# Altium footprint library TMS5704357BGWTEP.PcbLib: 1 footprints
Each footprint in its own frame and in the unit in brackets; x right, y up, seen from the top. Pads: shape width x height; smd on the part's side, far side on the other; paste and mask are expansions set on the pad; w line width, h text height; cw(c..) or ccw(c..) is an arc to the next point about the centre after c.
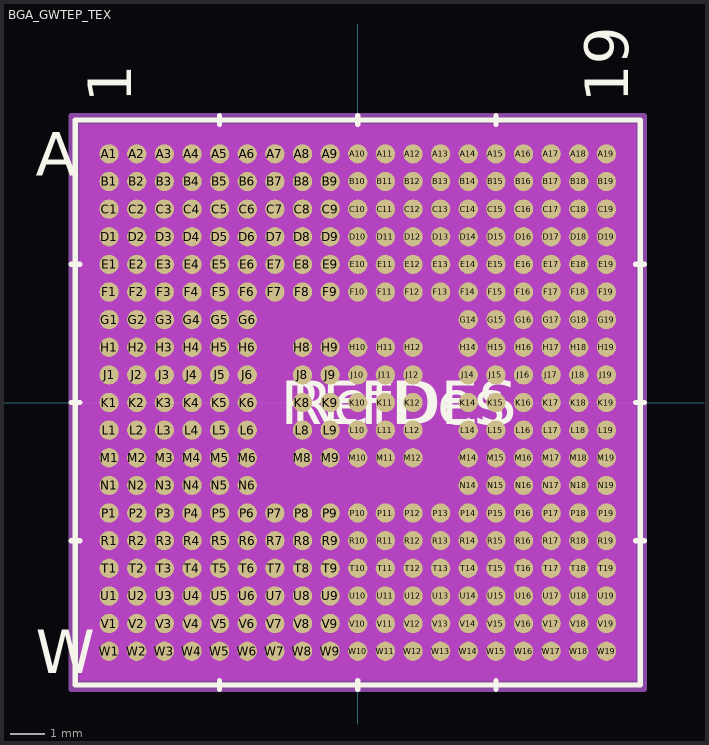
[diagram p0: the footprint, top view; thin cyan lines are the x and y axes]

## BGA_GWTEP_TEX [mil]
pads (337):
  round 22 smd paste+0 mask+0: A1(-283.46,283.5) A2(-251.97,283.5) A3(-220.47,283.5) A4(-188.98,283.5) A5(-157.48,283.5) A6(-125.98,283.5) A7(-94.49,283.5) A8(-62.99,283.5) A9(-31.5,283.5) A10(0,283.5) A11(31.5,283.5) A12(62.99,283.5) A13(94.49,283.5) A14(125.98,283.5) A15(157.48,283.5) A16(188.98,283.5) A17(220.47,283.5) A18(251.97,283.5) A19(283.46,283.5) B1(-283.46,252) B2(-251.97,252) B3(-220.47,252) B4(-188.98,252) B5(-157.48,252) B6(-125.98,252) B7(-94.49,252) B8(-62.99,252) B9(-31.5,252) B10(0,252) B11(31.5,252) B12(62.99,252) B13(94.49,252) B14(125.98,252) B15(157.48,252) B16(188.98,252) B17(220.47,252) B18(251.97,252) B19(283.46,252) C1(-283.46,220.5) C2(-251.97,220.5) C3(-220.47,220.5) C4(-188.98,220.5) C5(-157.48,220.5) C6(-125.98,220.5) C7(-94.49,220.5) C8(-62.99,220.5) C9(-31.5,220.5) C10(0,220.5) C11(31.5,220.5) C12(62.99,220.5) C13(94.49,220.5) C14(125.98,220.5) C15(157.48,220.5) C16(188.98,220.5) C17(220.47,220.5) C18(251.97,220.5) C19(283.46,220.5) D1(-283.46,189) D2(-251.97,189) D3(-220.47,189) D4(-188.98,189) D5(-157.48,189) D6(-125.98,189) D7(-94.49,189) D8(-62.99,189) D9(-31.5,189) D10(0,189) D11(31.5,189) D12(62.99,189) D13(94.49,189) D14(125.98,189) D15(157.48,189) D16(188.98,189) D17(220.47,189) D18(251.97,189) D19(283.46,189) E1(-283.46,157.5) E2(-251.97,157.5) E3(-220.47,157.5) E4(-188.98,157.5) E5(-157.48,157.5) E6(-125.98,157.5) E7(-94.49,157.5) E8(-62.99,157.5) E9(-31.5,157.5) E10(0,157.5) E11(31.5,157.5) E12(62.99,157.5) E13(94.49,157.5) E14(125.98,157.5) E15(157.48,157.5) E16(188.98,157.5) E17(220.47,157.5) E18(251.97,157.5) E19(283.46,157.5) F1(-283.46,126) F2(-251.97,126) F3(-220.47,126) F4(-188.98,126) F5(-157.48,126) F6(-125.98,126) F7(-94.49,126) F8(-62.99,126) F9(-31.5,126) F10(0,126) F11(31.5,126) F12(62.99,126) F13(94.49,126) F14(125.98,126) F15(157.48,126) F16(188.98,126) F17(220.47,126) F18(251.97,126) F19(283.46,126) G1(-283.46,94.5) G2(-251.97,94.5) G3(-220.47,94.5) G4(-188.98,94.5) G5(-157.48,94.5) G6(-125.98,94.5) G14(125.98,94.5) G15(157.48,94.5) G16(188.98,94.5) G17(220.47,94.5) G18(251.97,94.5) G19(283.46,94.5) H1(-283.46,63) H2(-251.97,63) H3(-220.47,63) H4(-188.98,63) H5(-157.48,63) H6(-125.98,63) H8(-62.99,63) H9(-31.5,63) H10(0,63) H11(31.5,63) H12(62.99,63) H14(125.98,63) H15(157.48,63) H16(188.98,63) H17(220.47,63) H18(251.97,63) H19(283.46,63) J1(-283.46,31.5) J2(-251.97,31.5) J3(-220.47,31.5) J4(-188.98,31.5) J5(-157.48,31.5) J6(-125.98,31.5) J8(-62.99,31.5) J9(-31.5,31.5) J10(0,31.5) J11(31.5,31.5) J12(62.99,31.5) J14(125.98,31.5) J15(157.48,31.5) J16(188.98,31.5) J17(220.47,31.5) J18(251.97,31.5) J19(283.46,31.5) K1(-283.46,0) K2(-251.97,0) K3(-220.47,0) K4(-188.98,0) K5(-157.48,0) K6(-125.98,0) K8(-62.99,0) K9(-31.5,0) K10(0,0) K11(31.5,0) K12(62.99,0) K14(125.98,0) K15(157.48,0) K16(188.98,0) K17(220.47,0) K18(251.97,0) K19(283.46,0) L1(-283.46,-31.5) L2(-251.97,-31.5) L3(-220.47,-31.5) L4(-188.98,-31.5) L5(-157.48,-31.5) L6(-125.98,-31.5) L8(-62.99,-31.5) L9(-31.5,-31.5) L10(0,-31.5) L11(31.5,-31.5) L12(62.99,-31.5) L14(125.98,-31.5) L15(157.48,-31.5) L16(188.98,-31.5) L17(220.47,-31.5) L18(251.97,-31.5) L19(283.46,-31.5) M1(-283.46,-63) M2(-251.97,-63) M3(-220.47,-63) M4(-188.98,-63) M5(-157.48,-63) M6(-125.98,-63) M8(-62.99,-63) M9(-31.5,-63) M10(0,-63) M11(31.5,-63) M12(62.99,-63) M14(125.98,-63) M15(157.48,-63) M16(188.98,-63) M17(220.47,-63) M18(251.97,-63) M19(283.46,-63) N1(-283.46,-94.5) N2(-251.97,-94.5) N3(-220.47,-94.5) N4(-188.98,-94.5) N5(-157.48,-94.5) N6(-125.98,-94.5) N14(125.98,-94.5) N15(157.48,-94.5) N16(188.98,-94.5) N17(220.47,-94.5) N18(251.97,-94.5) N19(283.46,-94.5) P1(-283.46,-126) P2(-251.97,-126) P3(-220.47,-126) P4(-188.98,-126) P5(-157.48,-126) P6(-125.98,-126) P7(-94.49,-126) P8(-62.99,-126) P9(-31.5,-126) P10(0,-126) P11(31.5,-126) P12(62.99,-126) P13(94.49,-126) P14(125.98,-126) P15(157.48,-126) P16(188.98,-126) P17(220.47,-126) P18(251.97,-126) P19(283.46,-126) R1(-283.46,-157.5) R2(-251.97,-157.5) R3(-220.47,-157.5) R4(-188.98,-157.5) R5(-157.48,-157.5) R6(-125.98,-157.5) R7(-94.49,-157.5) R8(-62.99,-157.5) R9(-31.5,-157.5) R10(0,-157.5) R11(31.5,-157.5) R12(62.99,-157.5) R13(94.49,-157.5) R14(125.98,-157.5) R15(157.48,-157.5) R16(188.98,-157.5) R17(220.47,-157.5) R18(251.97,-157.5) R19(283.46,-157.5) T1(-283.46,-189) T2(-251.97,-189) T3(-220.47,-189) T4(-188.98,-189) T5(-157.48,-189) T6(-125.98,-189) T7(-94.49,-189) T8(-62.99,-189) T9(-31.5,-189) T10(0,-189) T11(31.5,-189) T12(62.99,-189) T13(94.49,-189) T14(125.98,-189) T15(157.48,-189) T16(188.98,-189) T17(220.47,-189) T18(251.97,-189) T19(283.46,-189) U1(-283.46,-220.5) U2(-251.97,-220.5) U3(-220.47,-220.5) U4(-188.98,-220.5) U5(-157.48,-220.5) U6(-125.98,-220.5) U7(-94.49,-220.5) U8(-62.99,-220.5) U9(-31.5,-220.5) U10(0,-220.5) U11(31.5,-220.5) U12(62.99,-220.5) U13(94.49,-220.5) U14(125.98,-220.5) U15(157.48,-220.5) U16(188.98,-220.5) U17(220.47,-220.5) U18(251.97,-220.5) U19(283.46,-220.5) V1(-283.46,-252) V2(-251.97,-252) V3(-220.47,-252) V4(-188.98,-252) V5(-157.48,-252) V6(-125.98,-252) V7(-94.49,-252) V8(-62.99,-252) V9(-31.5,-252) V10(0,-252) V11(31.5,-252) V12(62.99,-252) V13(94.49,-252) V14(125.98,-252) V15(157.48,-252) V16(188.98,-252) V17(220.47,-252) V18(251.97,-252) V19(283.46,-252) W1(-283.46,-283.5) W2(-251.97,-283.5) W3(-220.47,-283.5) W4(-188.98,-283.5) W5(-157.48,-283.5) W6(-125.98,-283.5) W7(-94.49,-283.5) W8(-62.99,-283.5) W9(-31.5,-283.5) W10(0,-283.5) W11(31.5,-283.5) W12(62.99,-283.5) W13(94.49,-283.5) W14(125.98,-283.5) W15(157.48,-283.5) W16(188.98,-283.5) W17(220.47,-283.5) W18(251.97,-283.5) W19(283.46,-283.5)
Top Overlay:
  lines w6: -327,-157.5 -317,-157.5 ; -327,0 -317,0 ; -327,157.5 -317,157.5 ; -157.48,-327 -157.48,-317 ; -157.48,317 -157.48,327 ; 0,-327 0,-317 ; 0,317 0,327 ; 157.48,-327 157.48,-317 ; 157.48,317 157.48,327 ; 317,-157.5 327,-157.5 ; 317,0 327,0 ; 317,157.5 327,157.5 ; -322,-322 322,-322 322,322 -322,322 -322,-322
  text "A" at -367,258.5 h50
  text "W" at -367,-308.5 h50
  text "1" at -258.46,342 h50
  text "19" at 308.46,342 h50
  text "RefDes" at -75,-25 h50
  text "REFDES" at -87.5,-25 h50
Bottom Overlay:
  text "A" at -342,258.5 h50
  text "W" at -342,-308.5 h50
  text "1" at -308.46,342 h50
  text "19" at 258.46,342 h50
Keep-Out Layer:
  region: -316.71,-316.75 -316.71,316.75 316.71,316.75 316.71,-316.75
Mechanical 13:
  lines w1: -317,301.25 -301.25,317 ; -317,-317 317,-317 317,317 -317,317 -317,-317
  text "A" at -367,258.5 h50
  text "W" at -367,-308.5 h50
  text "1" at -258.46,342 h50
  text "19" at 308.46,342 h50
  text "RefDes2" at -87.5,-25 h50
Mechanical 15:
  region: 327,-327 -327,-327 -327,327 327,327
  lines w6: -327,-327 -327,327 327,327 327,-327 -327,-327
3D body "BGA_GWTEP_TEX.step": height 37.09, standoff -0.02, extent -317.01,-317.01 317.01,317.01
